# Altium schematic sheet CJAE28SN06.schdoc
size 127 x 101 mm
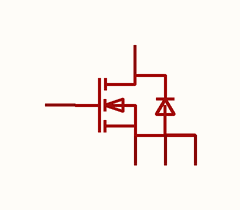
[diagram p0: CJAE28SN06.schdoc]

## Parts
Q?  cjae28sn06  [DFN-8_L3.0-W3.0-P0.65-LS3.1-BL]  (value not drawn)

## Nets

Not connected (* = marked no-connect by the designer): Q? 1(S) 2(S) 3(S) 4(G) 5(D)

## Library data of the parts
Q? = cjae28sn06: 数量:1个N沟道;漏源电压(Vdss):60V;连续漏极电流(Id):28A;导通电阻(RDS(on)):15mΩ@4.5V;耗散功率(Pd):32W;阈值电压(Vgs(th)):1V;; Manufacturer: CJ(江苏长电/长晶); AddInBom: yes; ModelId: 6ce275f581d94be6a0ecbe0ef507fbae; ModelTransform: 129.921,129.921,0,0,0,0,0,0,0; Number: 1个N沟道; Drain to Source Voltage: 60V; Current - Continuous Drain(Id): 28A; Pd - Power Dissipation: 32W; Gate Threshold Voltage (Vgs(th)): 1V; Gate Charge(Qg): 21.4nC@10V; Input Capacitance(Ciss): 1.083nF; Reverse Transfer Capacitance (Crss@Vds): 9.9pF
